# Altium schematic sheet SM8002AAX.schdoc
size 127 x 101 mm
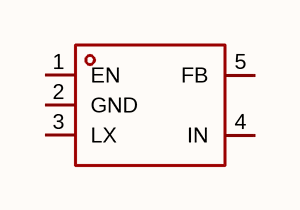
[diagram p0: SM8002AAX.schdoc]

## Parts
U?  sm8002aax  [SOT-23-5_L3.0-W1.5-P0.95-LS2.8-BL]  (value not drawn)

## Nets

Not connected (* = marked no-connect by the designer): U? 1(EN) 2(GND) 3(LX) 4(IN) 5(FB)

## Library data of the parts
U? = sm8002aax: 功能类型:降压型;工作电压:2.5V~5.5V;输出电压:600mV~5.5V;输出电流:2A;输出类型:可调;; Manufacturer: Silergy(矽力杰); AddInBom: yes; ModelId: 424d41c645fb4cc2a3598f66fad27964; ModelTransform: 118.11,110.236,0,0,0,0,0,0,0; Function: 降压型; Output Current: 2A; Frequency - Switching: 1.5MHz; Synchronous Rectifier: 是; Number of Outputs: 1; Topology: 降压式; Quiescent Current: 50uA; Switch tube (built-in/external): 内置; Output Type: 可调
